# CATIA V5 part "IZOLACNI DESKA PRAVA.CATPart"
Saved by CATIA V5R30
Part number: IZOLACNI DESKA PRAVA
Bounding box of the stored display mesh (mm): x 0 to 8.5, y -173 to 173, z -273 to 273
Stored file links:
  C:\Users\ondra\Desktop\PŘÍLOHA P III\CATIA\IZOLACNI DESKA PRAVA.CATPart
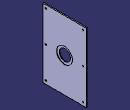
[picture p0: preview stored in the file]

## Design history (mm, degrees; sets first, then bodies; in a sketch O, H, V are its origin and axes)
Set1
  DatumSurface1 to DatumSurface6 "Z121/346"
  Join1: Elements (DatumSurface1; DatumSurface2; DatumSurface3; DatumSurface4; DatumSurface5; DatumSurface6)
Body1 (main body)
  DatumPoint1
  CloseSurface1: CloseElement Join1
  Sketch1 on {plane type Tangent, Support face of CloseSurface1, RefPoint vertex of DatumPoint1}, origin (-316, 148, -248), H (0, 1, 0), V (0, 0, -1)
    point P1 (0, 0)
    reference projected point E1 (0, 0) from vertex of DatumPoint1
    coincidence: E1 P1
  Hole1: placed by Sketch1, at (8.5, 148, -248) direction (-1, 0, 0), diameter 6, through (limit type 6), countersink depth 3.3, countersink angle 90
  Sketch2, origin (-316, 0, 0), H (0, 0, 1), V (0, 1, 0), geometry linked from another document
  UserPattern1: of Hole1, copies 6, at the points of Sketch2
  Plane1: type Offset, RefPlane yz-plane, Offset 8.5
  Plane2: stored without definition
  Sketch3 on Plane1, origin (8.5, 0, 0), H (0, 1, 0), V (0, 0, 1)
    circle A1 centre (0, 0) radius 45
    radius A1 = 45
  Pocket1: profile Sketch3, direction (-1, 0, 0), through (limit type 6)
  DatumSurface7 to DatumSurface9
  Sketch4 on Plane2, origin (-324.5, 0, 0), H (0, -1, 0), V (0, 0, 1)
    reference projected circle E1 centre (-33.775, 19.5) radius 3.75 from face of DatumSurface7
    reference projected circle E3 centre (0, -39) radius 3.75 from face of DatumSurface8
    reference projected circle E5 centre (33.775, 19.5) radius 3.75 from face of DatumSurface9
    point P1 (-33.775, 19.5)
    point P2 (33.775, 19.5)
    point P3 (0, -39)
    concentricity: P1 E1, P2 E5, P3 E3
  Sketch5 on Plane1, origin (8.5, 0, 0), H (0, 1, 0), V (0, 0, 1)
    circle A1 centre (0, 0) radius 62.5
    radius A1 = 62.5
  Pocket2: profile Sketch5, direction (-1, 0, 0), length 3.5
